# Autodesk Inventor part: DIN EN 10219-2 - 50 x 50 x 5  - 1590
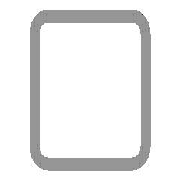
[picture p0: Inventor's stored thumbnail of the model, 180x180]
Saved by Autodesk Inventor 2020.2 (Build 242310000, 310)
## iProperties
_CCFamilyMember: 16
_CCFamilyDisplayName: DIN EN 10219-2 (Quadratisches Hohlprofil - Kaltgeformt) - Kaltgeformte, geschweißte Baustahl-Hohlprofile aus unlegiertem Feinkorn-Baustahl
_FrameMemberDoc: Frame Member File
_Version: 15.0.0
_GetPNFromCC: 1
IsCustomPart: 1
Created: 2019-01
Part Number: DIN EN 10219-2 - 50 x 50 x 5  - 1590
Material: Stahl, weich
Description: Kaltgeformte, geschweißte Baustahl-Hohlprofile aus unlegiertem Feinkorn-Baustahl
Document SubType Name: Modeling
Standard: DIN
Designer: lutzd
Standard Revision: 2006-07
Standards Organization: DIN
Language: de-DE
Size Designation: 50 x 50 x 5
Categories: <MemberInstance><Categories><Category DisplayName="Profile" InternalName="089c4875-fa83-4c05-b084-43b9cc11f5ed" Mnemonic="GRDR"><CategoryParameter DisplayName="
Stock Number: 50 x 50 x 5
Mass: 10416.2 g
Surface Area: 5334.75 cm^2
Volume: 1326.9 cm^3
Density: 7.85 g/cm^3
Appearance: Semi-Polished(8)
G_L: 1590,000 mm
G_W: 50,000 mm
G_H: 50,000 mm
DocNumber: ADSK-014418
Folder: .
Mass: 10,416 kg
VLT_Material: Stahl, weich
Dimensions: 50x50x1590 mm
Title: Profil-Bauteil
Author: lutzd
Revision Number: -
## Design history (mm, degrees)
node "Startebene"
node "Endebene"
sketch "Skizze"
  geometry: L1 (-25, -15)-(-25, 15); L2 (-15, 25)-(15, 25); L3 (25, 15)-(25, -15); L4 (15, -25)-(-15, -25); L5 (-15, 20)-(15, 20); L6 (20, 15)-(20, -15); L7 (15, -20)-(-15, -20); L8 (-20, -15)-(-20, 15); L9 (0, 37.899)-(0, -37.899) reference; L10 (-37.899, 0)-(37.899, 0) reference; A1 r 10 centre (-15, -15) between (-25, -15) and (-15, -25); A2 r 10 centre (-15, 15) between (-15, 25) and (-25, 15); A3 r 10 centre (15, 15) between (25, 15) and (15, 25); A4 r 10 centre (15, -15) between (15, -25) and (25, -15); A5 r 5 centre (-15, 15) between (-15, 20) and (-20, 15); A6 r 5 centre (15, 15) between (20, 15) and (15, 20); A7 r 5 centre (15, -15) between (15, -20) and (20, -15); A8 r 5 centre (-15, -15) between (-20, -15) and (-15, -20)
  constraints: 16 end point, 16 point on circle, 8 centre point, 8 tangent, 4 parallel, 3 equal radius, 2 perpendicular, 7 other
  dimensions: "d7" = 10 radius of A1 (= G_IR); "d10" = 50 distance between parallel lines of L2 L4 (= G_H); "d11" = 50 distance between parallel lines of L1 L3 (= G_W); "d12" = 5 distance between parallel lines of L3 L6 (= G_T); "d15" = 25 distance between parallel lines of L2 L10 (= 0.5 x d10); "d16" = 25 distance between parallel lines of L9 L3 (= 0.5 x d11)
extrude "Körper" new body sketch "Skizze" stored distance "d3" = 1590 (= G_L); taper "d4" = 0 deg
node "Driven Length"
  sketch "Sketch3"
    geometry: L1 (0, 0)-(10, 0) reference
    constraints: 2 end point, 1 horizontal
  workplane "Work Plane3"
  sketch "Sketch4"
    geometry: L1 (-2, 0)-(12, 0) reference; L2 (-2, 1590)-(12, 1590) reference
    dimensions: "d18" = 1590 distance between parallel lines of L1 L2 (derived)
sketch "Skizze5"
  geometry: L1 (1590, -30)-(1590, 0) reference; L2 (1590, -15)-(605, -16.659); 5 further points
  constraints: 3 point on line, 2 end point, 1 coincident, 1 midpoint
  dimensions: "d19" = 985 distance of L2.start L2.end; "d20" = 35 distance of point (605, -16.659) point (640, -16.601); "d21" = 35 distance of point (1468, -15.206) point (1503, -15.147) (= d20); "d22" = 87 distance from line of L1 point (1503, -15.147)
hole "Bohrung1" sketch "Skizze5" at (605, -16.659), (640, -16.601), (1503, -15.147), (1468, -15.206) diameter "d23" = 6.647; stored, may be unused: countersink angle "d27" = 90 deg, drill point angle "d29" = 118 deg; dims "d24" = 16, "d25" = 4, "d26" = 2, "d28" = 8
sketch "Skizze6"
  geometry: L1 (30, 0)-(0, 0) reference; L2 (15, 0)-(15, 80); 1 further point
  constraints: 2 end point, 1 coincident, 1 vertical
  dimensions: "d30" = 80 distance of L2.start L2.end
hole "Bohrung2" sketch "Skizze6" at (15, 80) diameter "d31" = 6.647; stored, may be unused: countersink angle "d35" = 90 deg, drill point angle "d37" = 118 deg; dims "d32" = 16, "d33" = 4, "d34" = 2, "d36" = 8
sketch "Skizze7"
  geometry: L1 (1590, 30)-(1590, 0) reference; L2 (1590, 15)-(1540, 15); 1 further point
  constraints: 2 end point, 1 coincident, 1 horizontal
  dimensions: "d38" = 50 distance of L2.start L2.end
hole "Bohrung3" sketch "Skizze7" at (1540, 15) diameter "d39" = 6.647; stored, may be unused: countersink angle "d43" = 90 deg, drill point angle "d45" = 118 deg; dims "d40" = 16, "d41" = 4, "d42" = 2, "d44" = 8
sketch "Skizze8"
  geometry: L1 (-30, 1590)-(0, 1590) reference; L2 (-15, 1590)-(-15, 1509); 4 further points
  constraints: 2 end point, 1 coincident, 1 point on line, 1 vertical, 1 vertical alignment
  dimensions: "d46" = 81 distance of L2.start L2.end; "d47" = 62 distance of point (-15, 1509) point (-15, 1571); "d55" = 424 vertical distance of point (-15, 1509) point (-9, 1085); "d56" = 6 horizontal distance of point (-15, 1509) point (-9, 1085); "d57" = 865 distance of point (-9, 220) point (-9, 1085)
hole "Bohrung4" sketch "Skizze8" at (-15, 1571), (-15, 1509), (-9, 1085), (-9, 220) diameter "d48" = 6.647; stored, may be unused: countersink angle "d52" = 90 deg, drill point angle "d54" = 118 deg; dims "d49" = 16, "d50" = 4, "d51" = 2, "d53" = 8
body "Solid1"
other parameters: "G_W" = 50 [user parameter; used in 1 equation term], "G_H" = 50 [user parameter; used in 1 equation term], "G_T" = 5 [user parameter; used in 1 equation term], "G_IR" = 10 [user parameter; used in 1 equation term], "G_L" = 1590 (= d18) [user parameter; used in 1 equation term], "G_OFFSET_START" = 0 [user parameter; used in 1 equation term], "G_OFFSET_END" = 0 [user parameter; used in 1 equation term], "d13" = 0 (computed from G_OFFSET_START), "d17" = 90 deg
